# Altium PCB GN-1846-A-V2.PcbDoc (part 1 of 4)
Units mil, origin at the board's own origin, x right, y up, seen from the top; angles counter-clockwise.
Board outline 11624.17 x 2384.02 mil, 4 copper layers (Top, GND, VCC, Bottom), stack 40.7 mil thick; 450 components, 346 nets, 1652 pads, 832 vias.
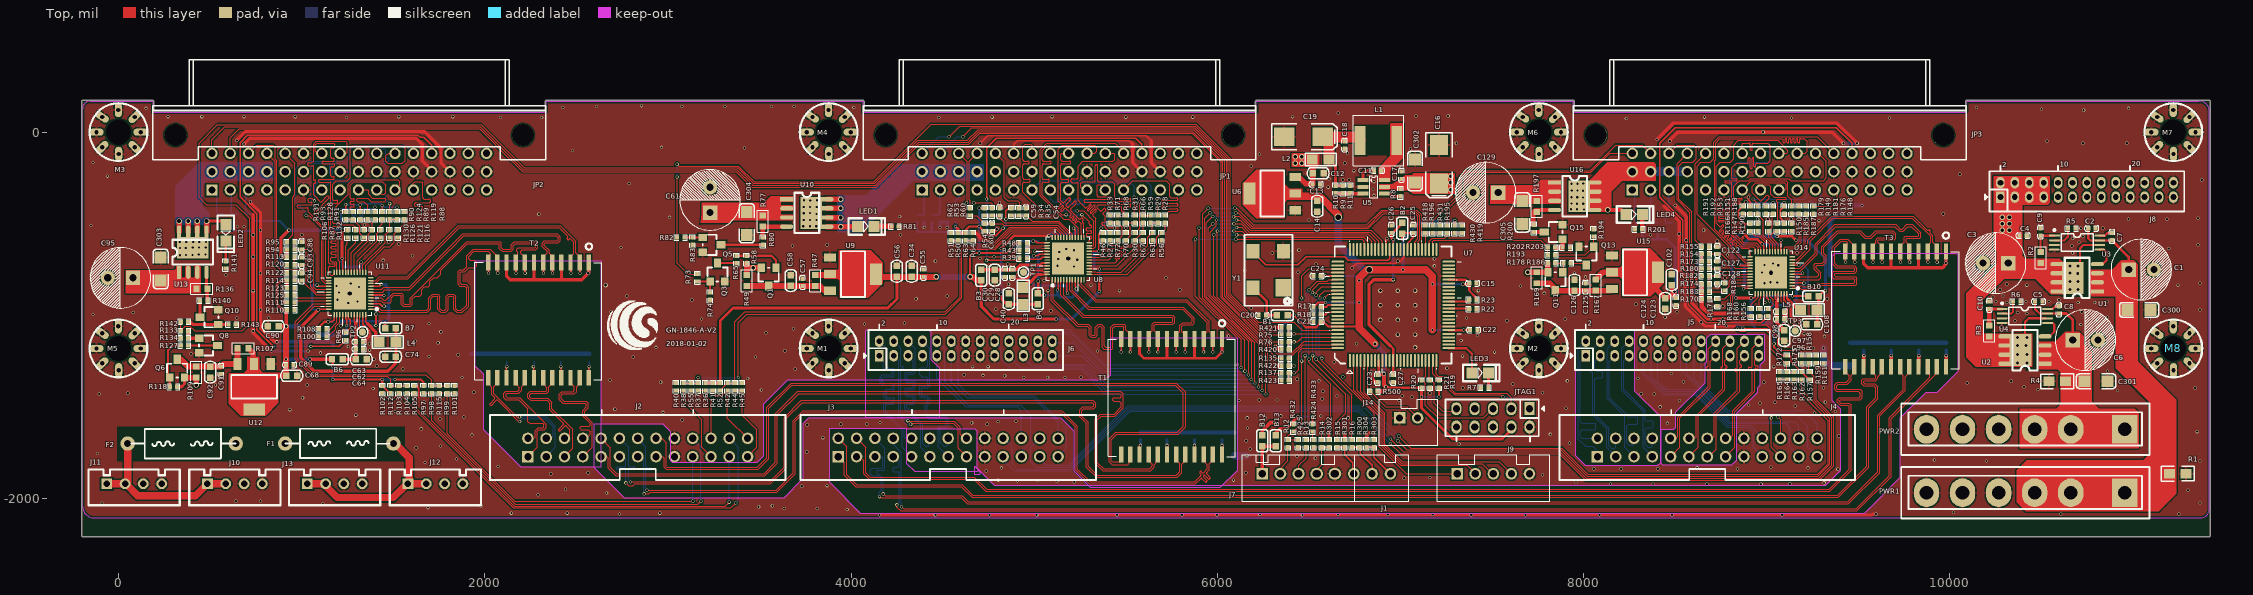
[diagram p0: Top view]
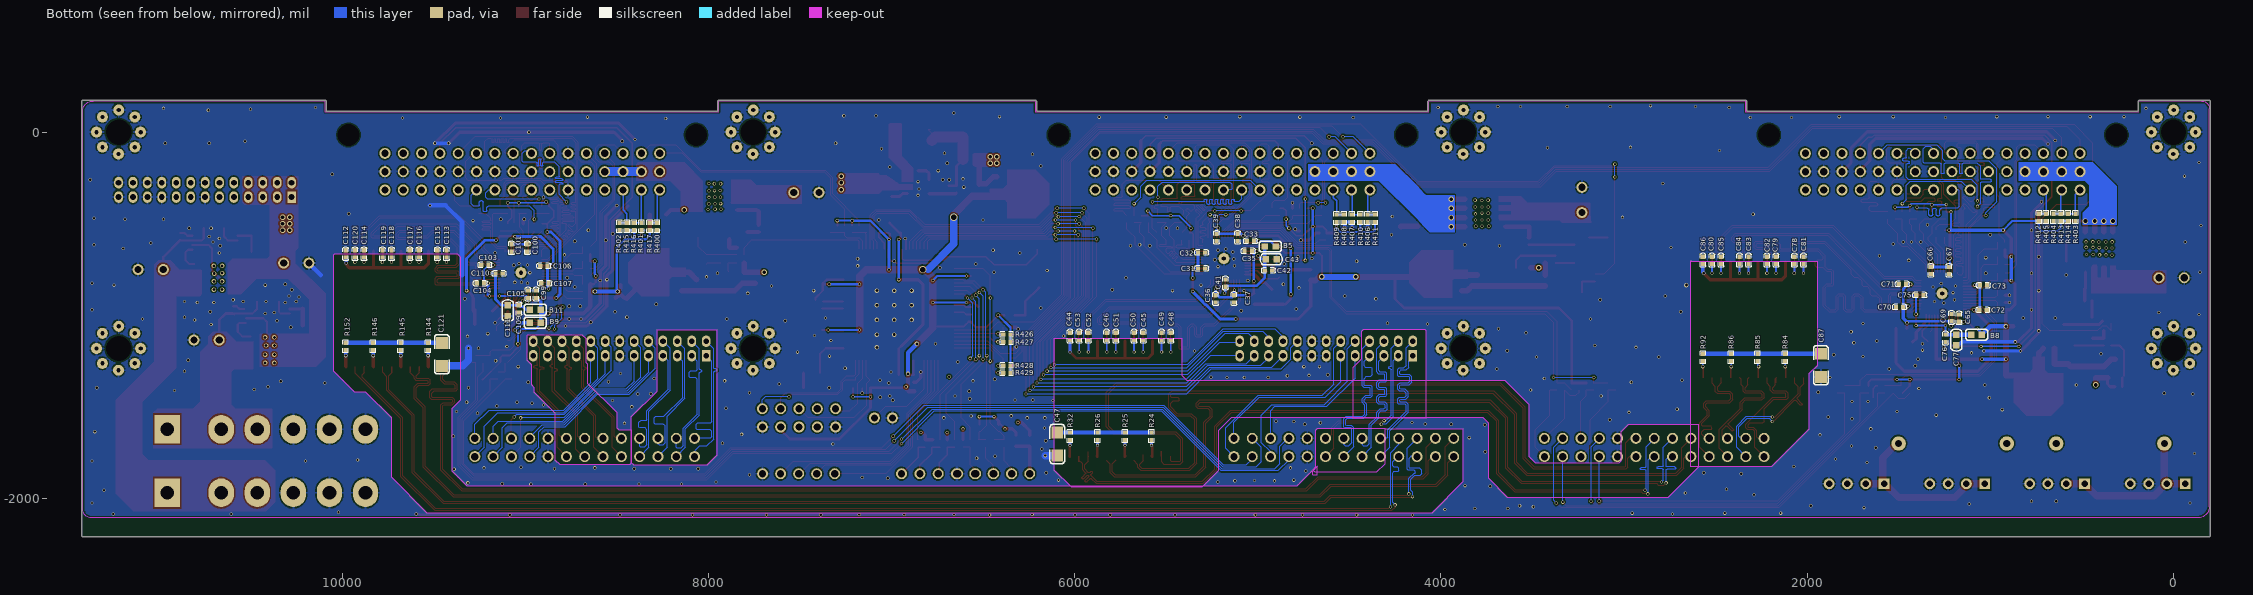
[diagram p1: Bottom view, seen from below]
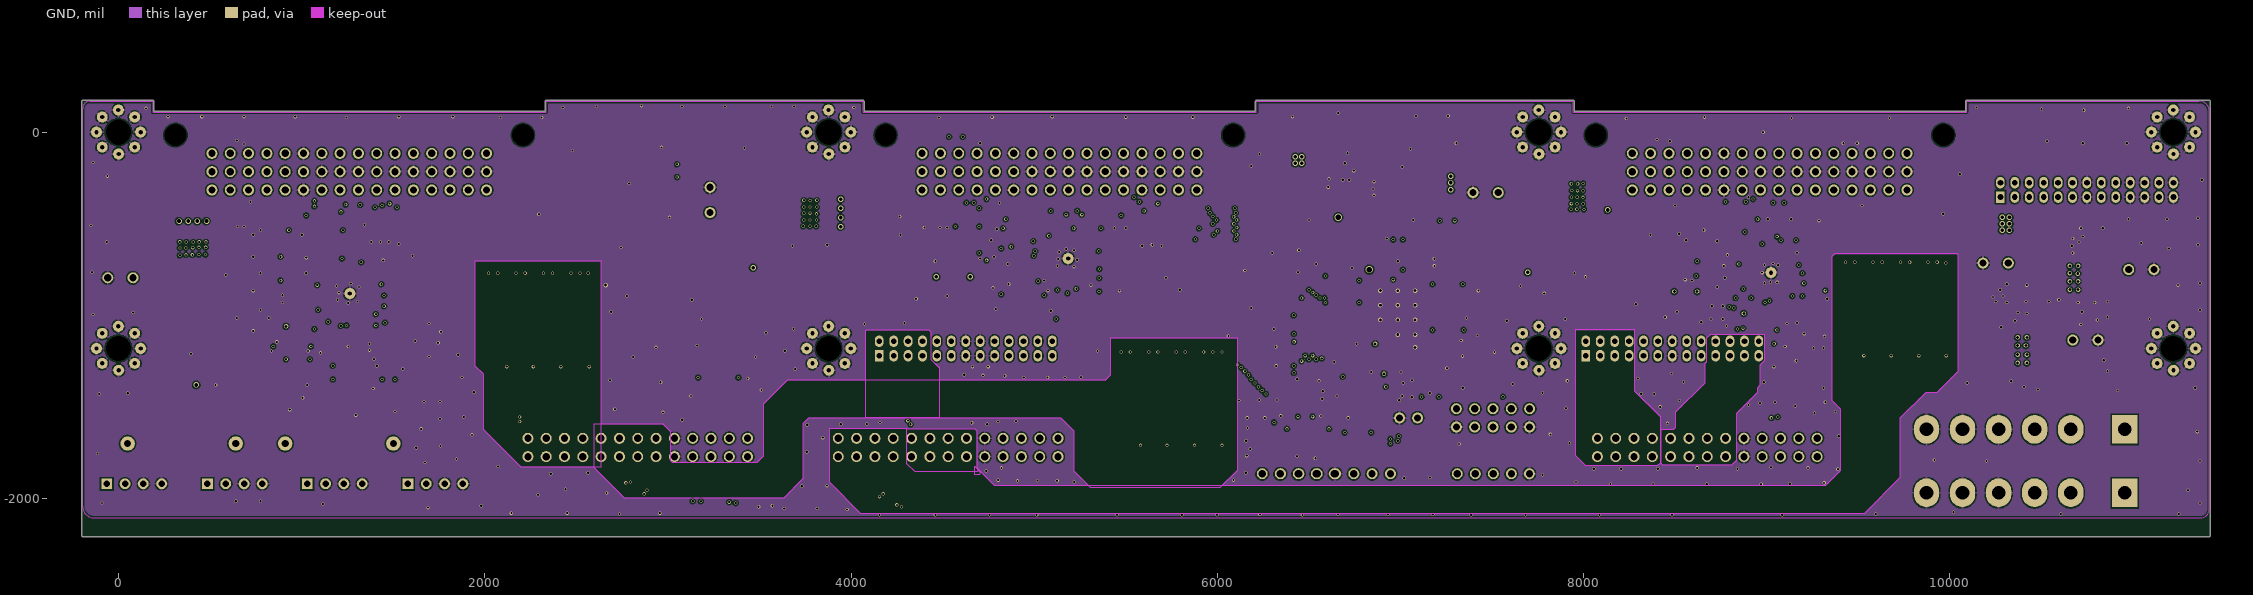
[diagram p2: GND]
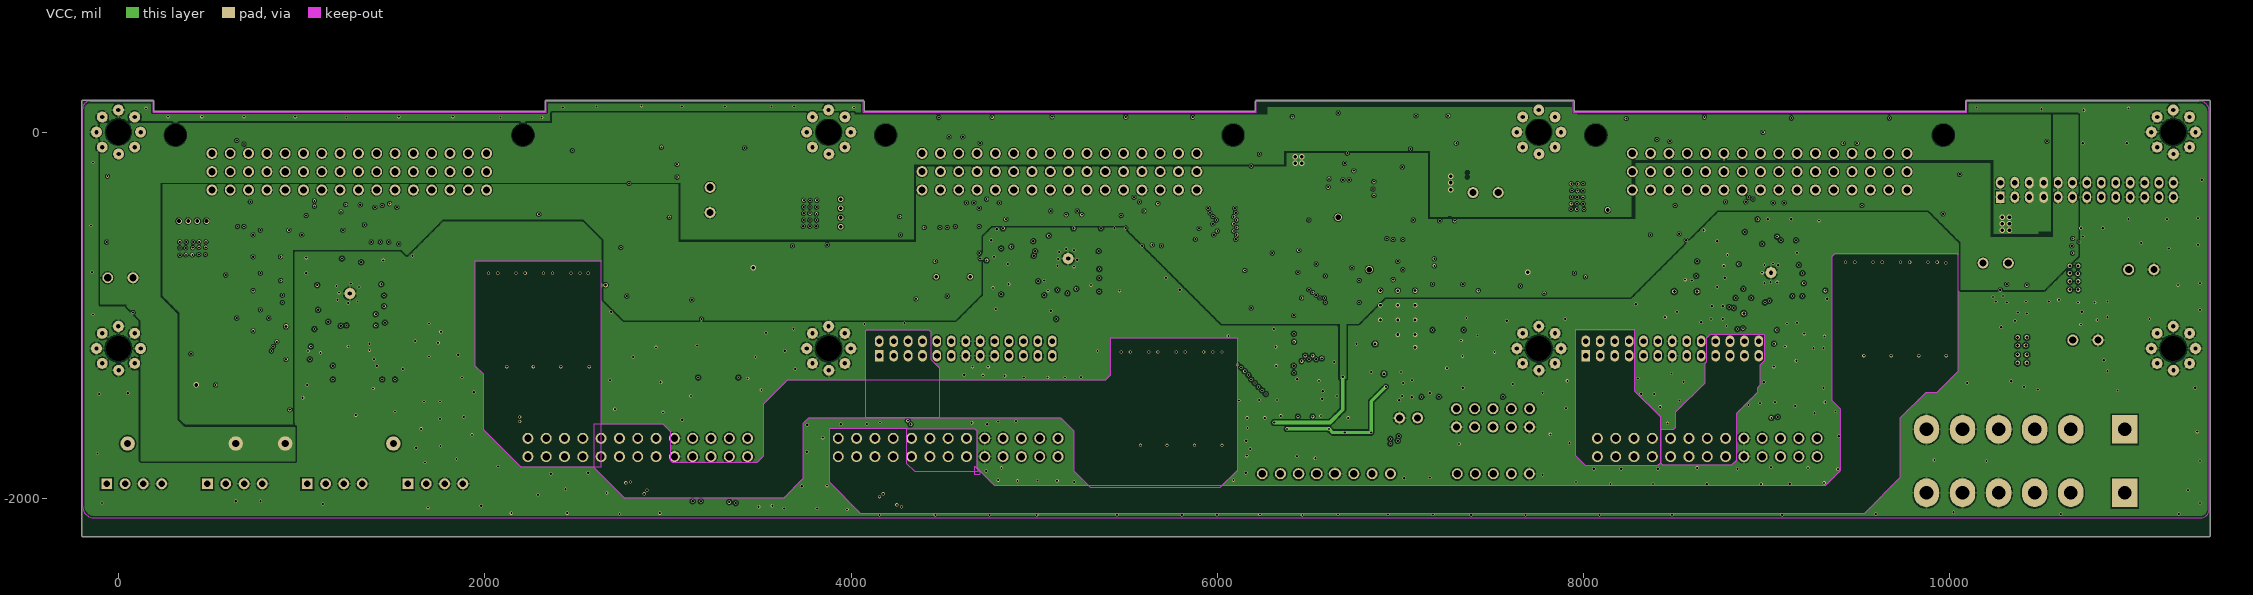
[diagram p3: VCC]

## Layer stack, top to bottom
Top: signal copper 1.35
Dielectric: core 10, FR-4, Dk 4.3
GND: signal copper 1.4
Dielectric: prepreg 12.6, FR-4, Dk 4.8
VCC: signal copper 1.4
Dielectric: core 12.6, FR-4, Dk 4.8
Bottom: signal copper 1.35

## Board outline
-201.85,-2204.72 -196.85,-2209.72 11417.32,-2209.72 11422.32,-2204.72 11422.32,169.29 11417.32,174.29 10090.55,174.29 10085.55,169.29 10085.55,115.24 7949.09,115.24 7949.09,169.29 7944.09,174.29 6212.6,174.29 6207.6,169.29 6207.6,115.24 4071.14,115.24 4071.14,169.29 4066.14,174.29 2334.25,174.29 2329.25,169.29 2329.25,115.24 193.19,115.24 193.19,169.29 188.19,174.29 -196.85,174.16 -201.85,169.16

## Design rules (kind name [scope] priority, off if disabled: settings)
Clearance "'Default' PADS rule_18" [All] p1: gap=5
ComponentClearance "'Default' PADS rule_12" [All] p1: gap=0 collisioncheckmode=3 verticalgap=0 showdistances=FALSE
FabricationTestPointUsage TestPointUsage [All] p1: valid=0 allowmultiple=FALSE
FabricationTestpoint Testpoint [All] p1: side=3 testpointundercomponent=TRUE minsize=40 maxsize=100 preferedsize=60 minholesize=0 maxholesize=40 preferedholesize=32 testpointgrid=1 allowsidetop=TRUE allowsidebottom=TRUE usegrid=TRUE gridtolerance=0.01
FlightTimeFalling "'Default' PADS rule_6" [All] p1: maximum=10.00
FlightTimeRising "'Default' PADS rule_5" [All] p1: maximum=10.00
Length "'Default' PADS rule" [All] p1: maxlimit=50000 minlimit=0
MaxMinImpedance "'Default' PADS rule_4" [All] p1: minimum=50.00 maximum=150.0
MinimumSolderMaskSliver [All] p1: minsoldermaskwidth=0
PlaneClearance "'Net' PADS rule_19" [InNet('GND')] p1: clearance=6
PlaneClearance "'Default' PADS rule_14" [All] p2: clearance=5
PlaneConnect "Power Plane Connect Style - pads with no thermal_20" [(Name='JTAG1-7') Or (Name='JTAG1-8') Or (Name='M1-1') Or (Name='M2-1') Or (Name='M3-1') Or (Name='M4-1') Or (Name='M5-1') Or (Name='M6-1') Or (Name='M7-1') Or (Name='M8-1')] p1: planeconnectstyle=Direct reliefexpansion=20 reliefentries=4 reliefconductorwidth=10 reliefairgap=10 // PAD - No Thermal Connect Rule
PlaneConnect "Power Plane Connect Style - pads with no thermal" [(Name='J7-5') Or (Name='JP1-A14') Or (Name='JP1-A15') Or (Name='JP1-A16') Or (Name='JP1-B5') Or (Name='JP1-B6') Or (Name='JP1-C1') Or (Name='JP1-C2') Or (Name='JP1-C3') Or (Name='JP1-C4') Or (Name='JP1-C5') Or (Name='JP1-C13') Or (Name='JP1-C14') Or (Name='JP1-C15') Or (Name='JP1-C16') Or (Name='JP1-0') Or (Name='JP1-0/2') Or (Name='JP2-A14') Or (Name='JP2-A15') Or (Name='JP2-A16') Or (Name='JP2-B5') Or (Name='JP2-B6') Or (Name='JP2-C1') Or (Name='JP2-C2') Or (Name='JP2-C3') Or (Name='JP2-C4') Or (Name='JP2-C5') Or (Name='JP2-C13') Or (Name='JP2-C14') Or (Name='JP2-C15') Or (Name='JP2-C16') Or (Name='JP2-0') Or (Name='JP2-0/2') Or (Name='JP3-A14') Or (Name='JP3-A15') Or (Name='JP3-A16') Or (Name='JP3-B5') Or (Name='JP3-B6') Or (Name='JP3-C1') Or (Name='JP3-C2') Or (Name='JP3-C3') Or (Name='JP3-C4') Or (Name='JP3-C5') Or (Name='JP3-C13') Or (Name='JP3-C14') Or (Name='JP3-C15') Or (Name='JP3-C16') Or (Name='JP3-0') Or (Name='JP3-0/2') Or (Name='JTAG1-6')] p2: planeconnectstyle=NoConnect reliefexpansion=20 reliefentries=4 reliefconductorwidth=10 reliefairgap=10 // PAD - No Thermal Connect Rule
PlaneConnect "Power Plane Connect Style - from global settings" [All] p3: planeconnectstyle=Direct reliefexpansion=20 reliefentries=4 reliefconductorwidth=15 reliefairgap=10
PolygonConnect PolygonConnect_1 [All vs isvia] p1: connectstyle=Direct reliefconductorwidth=10 reliefentries=4 polygonreliefangle="90 Angle"
PolygonConnect [All] p2: connectstyle=Relief reliefconductorwidth=10 reliefentries=4 polygonreliefangle="90 Angle"
RoomDefinition "P04 Power" [InComponentClass('P04 Power')] p1: confinementstyle=ConfineIn formatcopy=TRUE lockcomponents=FALSE outline -10196.85,-13767.85 -8196.85,-13767.85 -8196.85,-12767.85 -10196.85,-12767.85
RoomDefinition "P09 CONNECT & LED" [InComponentClass('P09 CONNECT & LED')] p2: confinementstyle=ConfineIn formatcopy=TRUE lockcomponents=FALSE outline -10196.85,-13767.85 -8196.85,-13767.85 -8196.85,-12767.85 -10196.85,-12767.85
RoomDefinition "P08 PHY 3" [InComponentClass('P08 PHY 3')] p3: confinementstyle=ConfineIn formatcopy=TRUE lockcomponents=FALSE outline -10196.85,-13767.85 -8196.85,-13767.85 -8196.85,-12767.85 -10196.85,-12767.85
RoomDefinition "P07 PHY 2" [InComponentClass('P07 PHY 2')] p4: confinementstyle=ConfineIn formatcopy=TRUE lockcomponents=FALSE outline -10196.85,-13767.85 -8196.85,-13767.85 -8196.85,-12767.85 -10196.85,-12767.85
RoomDefinition "P06 PHY 1" [InComponentClass('P06 PHY 1')] p5: confinementstyle=ConfineIn formatcopy=TRUE lockcomponents=FALSE outline -10196.85,-13767.85 -8196.85,-13767.85 -8196.85,-12767.85 -10196.85,-12767.85
RoutingLayers "'Default' PADS rule_10" [All] p1: top layer_v5=TRUE mid layer 1_v5=FALSE mid layer 2_v5=FALSE bottom layer_v5=TRUE
RoutingPriority "'Default' PADS rule_9" [All] p1: routingpriority=3
RoutingTopology "'Default' PADS rule_8" [All] p1: topology=Shortest
RoutingVias "'Default' PADS rule_11" [All] p1: holewidth=12 width=18 viastyle="Through Hole" minholewidth=12 minwidth=18 maxholewidth=12 maxwidth=18
SMDToCorner "'Default' PADS rule_16" [All] p1: distance=0
SMDToPlane "'Default' PADS rule_17" [All] p1: distance=50000
SilkToSilkClearance [All] p1: silktosilkclearance=0
SilkscreenOverComponentPads [All] p1: minsilkscreentomaskgap=0
SolderMaskExpansion [All] p1: expansion=4
Width "'Net' PADS rule" [InNet('GND')] p1: maxlimit=100 minlimit=5 preferedwidth=5
Width "'Default' PADS rule_13" [All] p2: maxlimit=100 minlimit=5 preferedwidth=5
17 further rules are at their usual default settings.

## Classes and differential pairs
component class "P09 CONNECT & LED": J2 J3 J4 J5 J6 J8 M1 M2 M3 M4 M5 M6 M7 M8
component class "P08 PHY 3": B9 B10 B11 C96 C97 C98 C99 C100 C101 C102 C103 C104 C105 C106 C107 C108 C109 C110 C111 C112 C113 C114 C115 C116 C117 C118 C119 C120 C121 C122 C123 C124 C125 C126 C127 C128 C129 C305 JP3 L5 LED4 Q11 Q13 Q15 R144 R145 R146 R147 R148 R149 R150 R151 R152 R153 R154 R155 R156 R157 R158 R159 R160 R161 R162 R163 R164 R165 R166 R167 R168 R169 R170 R171 R172 R173 R174 R175 R176 R178 R179 R180 R181 R182 R183 R184 R185 R186 R187 R188 R190 R191 R192 R193 R194 R195 R196 R197 R200 R201 R202 R203 R400 R401 R402 R415 R416 R417 R418 R419 R430 R431 T3 TP3 U14 U15 U16
component class "P07 PHY 2": B6 B7 B8 C62 C63 C64 C65 C66 C67 C68 C69 C70 C71 C72 C73 C74 C75 C76 C77 C78 C79 C80 C81 C82 C83 C84 C85 C86 C87 C88 C89 C90 C91 C92 C93 C94 C95 C303 JP2 L4 LED2 Q6 Q8 Q10 R84 R85 R86 R87 R88 R89 R90 R91 R92 R93 R94 R95 R96 R97 R98 R99 R100 R101 R102 R103 R104 R105 R106 R107 R108 R109 R110 R111 R112 R113 R114 R115 R116 R118 R119 R120 R121 R122 R123 R124 R125 R126 R127 R128 R130 R131 R132 R133 R134 R135 R136 R137 R140 R141 R142 R143 R403 R404 R405 R412 R413 R414 R422 R423 R428 R429 T2 TP2 U11 U12 U13
component class "P06 PHY 1": B3 B4 B5 C28 C29 C30 C31 C32 C33 C34 C35 C36 C37 C38 C39 C40 C41 C42 C43 C44 C45 C46 C47 C48 C49 C50 C51 C52 C53 C54 C55 C56 C57 C58 C59 C60 C61 C304 JP1 L3 LED1 Q1 Q3 Q5 R24 R25 R26 R27 R28 R29 R30 R31 R32 R33 R34 R35 R36 R37 R38 R39 R40 R41 R42 R43 R44 R45 R46 R47 R48 R49 R50 R51 R52 R53 R54 R55 R56 R58 R59 R60 R61 R62 R63 R64 R65 R66 R67 R68 R70 R71 R72 R73 R74 R75 R76 R77 R80 R81 R82 R83 R406 R407 R408 R409 R410 R411 R420 R421 R426 R427 T1 TP1 U8 U9 U10
component class "P05 CPLD": B1 B2 B12 B13 C20 C21 C22 C23 C24 C25 C26 C27 F1 F2 J1 J7 J9 J10 J11 J12 J13 J14 JTAG1 LED3 R7 R12 R13 R14 R15 R16 R17 R18 R19 R20 R21 R22 R23 R300 R301 R302 R303 R304 R424 R425 R432 R433 R500 U7 Y1
component class "P04 Power": C1 C2 C3 C4 C5 C6 C7 C8 C9 C10 C11 C12 C13 C14 C15 C16 C17 C18 C19 C300 C301 C302 L1 L2 PWR1 PWR2 R1 R2 R3 R4 R5 R6 R8 R9 R10 R11 U1 U2 U3 U4 U5 U6

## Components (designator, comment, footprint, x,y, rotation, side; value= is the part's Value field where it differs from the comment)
B1 "MGLB1608M600T3R0-LF" L0603 6355,-1000 r270 top
B2 "MGLB1608M600T3R0-LF" L0603 7010,-525 r180 top
B3 "MGLB1608M600T3R0-LF" L0603 4710,-780 r0 top
B4 "MGLB1608M600T3R0-LF" L0603 5020,-910 r0 top
B5 "MGLB1608M600T3R0-LF" L0603 4931.85,-624.16 r90 bottom
B6 "MGLB1608M600T3R0-LF" L0603 1195,-1240 r270 top
B7 "MGLB1608M600T3R0-LF" L0603 1485,-1070 r90 top
B8 "MGLB1608M600T3R0-LF" L0603 1075,-1105 r90 bottom
B9 "MGLB1608M600T3R0-LF" L0603 8945,-1040 r90 bottom
B10 "MGLB1608M600T3R0-LF" L0603 9255,-895 r90 top
B11 "MGLB1608M600T3R0-LF" L0603 8945,-970 r90 bottom
B12 "MGLB1608M600T3R0-LF" L0603 6245,-1685 r180 top
B13 "NC" L0603 6320,-1685 r180 top
C1 "220uF/25V/DIP" CE8X3.5 11045,-750 r0 top
C2 "0.1uF" 0402C 10755,-525 r0 top
C3 "220uF/25V/DIP" CE8X3.5 10250,-715 r180 top
C4 "0.1uF" 0402C 10380,-565 r0 top
C5 "0.1uF" 0402C 10465,-925 r0 top
C6 "220uF/25V/DIP" CE8X3.5 10740,-1135 r0 top
C7 "2200pF" 0402C 10885,-590 r90 top
C8 "2200pF" 0402C 10595,-990 r90 top
C9 "0.01uF" 0402C 10495,-565 r90 top
C10 "0.01uF" 0402C 10215,-965 r90 top
C11 "0.1uF/0603" 0402C 6855,-210 r0 top
C12 "10uF" C0603#1 6550,-225 r0 top
C13 "0.1uF" 0402C 6520,-285 r0 top
C14 "10uF" C0603#2 6545,-405 r270 top
C15 "0.1uF" 0402C 7375,-825 r0 top
C16 "22uF/25V/TD" C6032 7210,-280 r90 top
C17 "0.1uF" 0402C 7005,-255 r90 top
C18 "0.1uF" 0402C 6695,-50 r270 top
C19 "220uF/10V/TD" C6032 6575,-25 r180 top
C20 "0.1uF" 0402C 6225,-1000 r0 top
C21 "0.1uF" 0402C 6565,-1035 r180 top
C22 "0.1uF" 0402C 7380,-1080 r0 top
C23 "0.1uF" 0402C 6875,-1325 r270 top
C24 "0.1uF" 0402C 6565,-785 r180 top
C25 "0.1uF" 0402C 7070,-550 r90 top
C26 "0.1uF" 0402C 6950,-550 r90 top
C27 "0.1uF" 0402C 6960,-1325 r270 top
C28 "0.1uF" 0402C 4880,-750 r270 top
C29 "0.1uF" 0402C 4840,-750 r270 top
C30 "10uF" C0603#2 4785,-780 r270 top
C31 "0.1uF" 0402C 5326.38,-744.16 r180 bottom
C32 "0.1uF" 0402C 5326.38,-657.16 r180 bottom
C33 "0.1uF" 0402C 5020,-595 r0 bottom
C34 "10uF" C0603#2 4330,-760 r90 top
C35 "0.1uF" 0402C 5031.85,-649.16 r0 bottom
C36 "0.1uF" 0402C 5230,-890 r270 bottom
C37 "0.1uF" 0402C 5130,-890 r270 bottom
C38 "0.1uF" 0402C 5110,-555 r270 bottom
C39 "0.1uF" 0402C 5225,-555 r270 bottom
C40 "10uF" C0603#2 4860,-910 r90 top
C41 "0.1uF" 0402C 5176.85,-844.16 r90 bottom
C42 "0.1uF" 0402C 4961.38,-755 r180 bottom
C43 "10uF" C0603#2 4926.85,-694.16 r180 bottom
C44 "0.1uF" 0402C 6025,-1135 r90 bottom
C45 "nc" 0402C 5625,-1095 r270 bottom
C46 "nc" 0402C 5825,-1095 r270 bottom
C47 "1000pF/1KV" C1206 6095,-1640 r270 bottom
C48 "nc" 0402C 5475,-1095 r270 bottom
C49 "nc" 0402C 5525,-1095 r270 bottom
C50 "nc" 0402C 5675,-1095 r270 bottom
C51 "nc" 0402C 5775,-1095 r270 bottom
C52 "nc" 0402C 5925,-1095 r270 bottom
C53 "nc" 0402C 5975,-1095 r270 bottom
C54 "0.1uF" 0402C 4955,-415 r270 top
C55 "0.1uF" 0402C 4395,-790 r90 top
C56 "10uF" C0603#2 4250,-760 r90 top
C57 "0.1uF" 0402C 3735,-840 r90 top
C58 "10uF" C0603#2 3670,-810 r90 top
C59 "nc" 0402C 4810,-415 r270 top
C60 "nc" 0402C 4770,-540 r90 top
C61 "220uF/25V/DIP" CE8X3.5 3230,-370 r90 top
C62 "0.1uF" 0402C 1295,-1185 r0 top
C63 "0.1uF" 0402C 1295,-1145 r0 top
C64 "10uF" C0603#2 1325,-1240 r0 top
C65 "0.1uF" 0402C 1170,-1035 r90 bottom
C66 "0.1uF" 0402C 1325,-735 r270 bottom
C67 "0.1uF" 0402C 1225,-735.47 r270 bottom
C68 "10uF" C0603#2 945,-1330 r0 top
C69 "0.1uF" 0402C 1212.56,-1032.91 r90 bottom
C70 "0.1uF" 0402C 1475,-955 r0 bottom
C71 "0.1uF" 0402C 1460,-830 r0 bottom
C72 "0.1uF" 0402C 1059.83,-970.17 r180 bottom
C73 "0.1uF" 0402C 1057.68,-835.84 r180 bottom
C74 "10uF" C0603#2 1485,-1225 r180 top
C75 "0.1uF" 0402C 1404.53,-890 r180 bottom
C76 "0.1uF" 0402C 1245,-1105.47 r270 bottom
C77 "10uF" C0603#2 1185,-1135 r270 bottom
C78 "nc" 0402C 2070,-680 r270 bottom
C79 "nc" 0402C 2170,-680 r270 bottom
C80 "nc" 0402C 2520,-680 r270 bottom
C81 "nc" 0402C 2020,-680 r270 bottom
C82 "nc" 0402C 2220,-680 r270 bottom
C83 "nc" 0402C 2320,-680 r270 bottom
C84 "nc" 0402C 2370,-680 r270 bottom
C85 "nc" 0402C 2470,-680 r270 bottom
C86 "0.1uF" 0402C 2570,-720 r90 bottom
C87 "1000pF/1KV" C1206 1925,-1210 r270 bottom
C88 "0.1uF" 0402C 1000,-600 r270 top
C89 "0.1uF" 0402C 915,-1270 r0 top
C90 "10uF" C0603#2 845,-1060 r180 top
C91 "0.1uF" 0402C 560,-1280 r270 top
C92 "10uF" C0603#2 500,-1310 r270 top
C93 "nc" 0402C 1000,-685 r270 top
C94 "nc" 0402C 1000,-770 r270 top
C95 "220uF/25V/DIP" CE8X3.5 10,-795 r180 top
C96 "0.1uF" 0402C 9055,-1020 r0 top
C97 "0.1uF" 0402C 9055,-980 r0 top
C98 "10uF" C0603#2 9095,-1110 r270 top
C99 "0.1uF" 0402C 8940,-905 r90 bottom
C100 "0.1uF" 0402C 8988.39,-612.32 r270 bottom
C101 "0.1uF" 0402C 9075,-612.32 r270 bottom
C102 "10uF" C0603#2 8480,-805 r90 top
C103 "0.1uF" 0402C 9200,-725 r0 bottom
C104 "0.1uF" 0402C 9225,-825 r0 bottom
C105 "0.1uF" 0402C 8985,-905 r90 bottom
C106 "0.1uF" 0402C 8878.02,-730 r0 bottom
C107 "0.1uF" 0402C 8872.55,-825 r0 bottom
C108 "10uF" C0603#2 9245,-1050 r180 top
C109 "0.1uF" 0402C 9035,-945 r270 bottom
C110 "0.1uF" 0402C 9162.55,-772.22 r180 bottom
C111 "10uF" C0603#2 9095,-975 r270 bottom
C112 "0.1uF" 0402C 9980,-685 r90 bottom
C113 "nc" 0402C 9430,-645 r270 bottom
C114 "nc" 0402C 9880,-645 r270 bottom
C115 "nc" 0402C 9480,-645 r270 bottom
C116 "nc" 0402C 9580,-645 r270 bottom
C117 "nc" 0402C 9630,-645 r270 bottom
C118 "nc" 0402C 9730,-645 r270 bottom
C119 "nc" 0402C 9780,-645 r270 bottom
C120 "nc" 0402C 9930,-645 r270 bottom
C121 "1000pF/1KV" C1206 9455,-1150 r270 bottom
C122 "0.1uF" 0402C 8730,-625 r270 top
C123 "0.1uF" 0402C 8505,-905 r270 top
C124 "10uF" C0603#2 8445,-935 r270 top
C125 "0.1uF" 0402C 8010,-865 r90 top
C126 "10uF" C0603#2 7950,-835 r90 top
C127 "nc" 0402C 8730,-705 r270 top
C128 "nc" 0402C 8730,-825 r90 top
C129 "220uF/25V/DIP" CE8X3.5 7465,-330 r180 top
C300 "0.1uF" C1206 10970,-970 r0 top
C301 "0.1uF" C1206 10735,-1360 r0 top
C302 "nc" C1206 7080,-275 r90 top
C303 "10UF" C1206 230,-810 r90 top
C304 "10UF" C1206 3430,-435 r270 top
C305 "10UF" C1206 7665,-375 r270 top
F1 "Fuse 1" F15 910,-1700 r0 top
F2 "Fuse 1" F15 640,-1700 r180 top
J1 "8PIN_2.54MM" CON8_2D54MM_G 6245,-1865 r0 top
J2 "CON26A" HERDER2X13 2235,-1771.65 r0 top locked
J3 "CON26A" HERDER2X13 3930,-1771.65 r0 top locked
J4 "CON26A" HERDER2X13 8075,-1771.65 r0 top locked
J5 "CON14" HERDER13X2-2.0 8011.81,-1220.47 r0 top locked
J6 "CON14" HERDER13X2-2.0 4153.54,-1220.47 r0 top
J7 "5PIN_2.54MM" CON5_2D54MM_G 6245,-1865 r0 top
J8 "CON14" HERDER13X2-2.0 10275.59,-354.33 r0 top locked
J9 "5PIN_2.54MM" CON5_2D54MM_G 7310,-1865 r0 top
J10 "4PIN_2.54MM" SIP4 485,-1920 r0 top
J11 "4PIN_2.54MM" SIP4 -65,-1920 r0 top
J12 "4PIN_2.54MM" SIP4 1580,-1920 r0 top
J13 "4PIN_2.54MM" SIP4 1030,-1920 r0 top
J14 "2PIN_2.54MM" CN2 6995,-1560 r0 top
JP1 "3348RFRS-029" 3348RFRS-029 5137.8,-215.41 r180 top locked
JP2 "3348RFRS-029" 3348RFRS-029 1259.84,-215.52 r180 top locked
JP3 "3348RFRS-029" 3348RFRS-029 9015.75,-215.52 r180 top locked
JTAG1 "2x5_2.54MM" HERDER5X2 7705,-1510 r180 top
L1 "MPIT6045-100M-LF" MPI6045 6880,-45 r180 top
L2 "MPIT5040-3R3N-LF" FB0805 6610,-150 r180 top
L3 "CBC3225T4R7MR" FB0805 4940,-940 r90 top
L4 "CBC3225T4R7MR" FB0805 1515,-1145 r180 top
L5 "CBC3225T4R7MR" FB0805 9275,-970 r180 top
LED1 "GRE/0805" LED0805 4125,-515 r180 top
LED2 "GRE/0805" LED0805 585,-595 r90 top
LED3 "GRE/0805" LED0805 7480,-1315 r180 top
LED4 "GRE/0805" LED0805 8320,-450 r180 top
M1 "HOLE-8STARS" HK 3877.95,-1181.1 r0 top locked
M2 "HOLE-8STARS" HK 7755.91,-1181.1 r0 top locked
M3 "HOLE-8STARS" HK 0,0 r0 top locked
M4 "HOLE-8STARS" HK 3877.95,0 r0 top locked
M5 "HOLE-8STARS" HK 0,-1181.1 r0 top locked
M6 "HOLE-8STARS" HK 7755.91,0 r0 top locked
M7 "HOLE-8STARS" HK 11220.47,0 r0 top locked
M8 "HOLE-8STARS" HK 11220.47,-1181.1 r0 top locked
PWR1 "POWER_6P" TJC2-6 10955,-1968.5 r180 top
PWR2 "POWER_6P" TJC2-6 10955,-1622.05 r180 top
Q1 "P6403FMG" SOT23 3550,-790 r180 top
Q3 "MMBT3904" SOT23 3270,-765 r0 top
Q5 "MMBT3904" SOT23 3240,-615 r270 top
Q6 "P6403FMG" SOT23 320,-1290 r0 top
Q8 "MMBT3904" SOT23 490,-1165 r270 top
Q10 "MMBT3904" SOT23 495,-1010 r90 top
Q11 "P6403FMG" SOT23 7845,-815 r180 top
Q13 "MMBT3904" SOT23 8015,-675 r180 top
Q15 "MMBT3904" SOT23 7835,-545 r90 top
R1 "nc" 0805 11200,-1865 r270 top
R2 "10" R0603 10495,-685 r90 top
R3 "10" R0603 10215,-1085 r90 top
R4 "nc" 0805 10630,-1360 r90 top
R5 "40.2K/1%" 0402R 10645,-525 r0 top
R6 "40.2K/1%" 0402R 10345,-925 r0 top
R7 "5.1K" 0402R 7440,-1395 r0 top
R8 "100K" 0402R 7000,-310 r270 top
R9 "62K/1%" 0402R 6685.51,-292.35 r270 top
R10 "nc" 0402R 6645.51,-292.35 r270 top
R11 "7.5K/1%" 0402R 6725.51,-332.35 r90 top
R12 "100" 0402R 6385,-1680 r270 top
R13 "100" 0402R 6485,-1680 r270 top
R14 "100" 0402R 6570,-1680 r270 top
R15 "100" 0402R 6655,-1680 r270 top
R16 "100" 0402R 6735,-1680 r270 top
R17 "nc" 0402R 6525,-955 r0 top
R18 "nc" 0402R 6525,-995 r0 top
R19 "4.7K" 0402R 7210,-1395 r90 top
R20 "4.7K" 0402R 7115,-1395 r90 top
R21 "4.7K" 0402R 7160,-1355 r270 top
R22 "nc" 0402R 7375,-965 r0 top
R23 "nc" 0402R 7375,-915 r0 top
R24 "75" 0402R 5580,-1680 r90 bottom
R25 "75" 0402R 5725,-1680 r90 bottom
R26 "75" 0402R 5875,-1680 r90 bottom
R27 "33" 0402R 5415,-550 r270 top
R28 "33" 0402R 5715,-455 r270 top
R29 "33" 0402R 5675,-455 r270 top
R30 "33" 0402R 5550,-550 r270 top
R31 "33" 0402R 5550,-455 r270 top
R32 "75" 0402R 6025,-1680 r90 bottom
R33 "33" 0402R 5415,-455 r270 top
R34 "nc" 0402R 4875,-415 r270 top
R35 "33" 0402R 4915,-415 r270 top
R36 "nc" 0402R 3205,-1370 r270 top
R37 "0" 0402R 3165,-1370 r270 top
R38 "nc" 0402R 3085,-1370 r270 top
R39 "33" 0402R 4920,-690 r0 top
R40 "4.7K" 0402R 3045,-1370 r270 top
R41 "4.7K" 0402R 3245,-1370 r270 top
R42 "nc" 0402R 3325,-1370 r270 top
R43 "2.49K/1%" 0402R 4920,-645 r0 top
R44 "0" 0402R 3365,-1370 r270 top
R45 "nc" 0402R 3405,-1370 r270 top
R46 "4.7K" 0402R 5375,-590 r90 top
R47 "nc" R0603 3805,-810 r270 top
R48 "4.7K" 0402R 4960,-605 r180 top
R49 "nc" R0603 3430,-810 r90 top
R50 "4.7K" 0402R 4585,-590 r90 top
R51 "nc" 0402R 4545,-590 r90 top
R52 "4.7K" 0402R 3285,-1410 r90 top
R53 "1.5K" 0402R 4730,-455 r90 top
R54 "1.5K" 0402R 4730,-500 r270 top
R55 "4.7K" 0402R 3125,-1370 r270 top
R56 "4.7K" 0402R 5695,-550 r270 top
R58 "100K" 0402R 3430,-715 r90 top
R59 "4.7K" 0402R 5635,-495 r90 top
R60 "33" 0402R 4770,-415 r270 top
R61 "nc" 0402R 5645,-550 r270 top
R62 "33" 0402R 4650,-415 r270 top
R63 "4.7K" 0402R 4625,-590 r90 top
R64 "nc" 0402R 4665,-590 r90 top
R65 "10K" 0402R 3375,-675 r270 top
R66 "4.7K" 0402R 5595,-495 r90 top
R67 "nc" 0402R 5595,-550 r270 top
R68 "4.7K" 0402R 5500,-495 r90 top
R70 "nc" 0402R 5500,-590 r90 top
R71 "4.7K" 0402R 5455,-495 r90 top
R72 "nc" 0402R 5455,-590 r90 top
R73 "2K" 0402R 3160,-815 r90 top
R74 "1K" 0402R 3230,-915 r90 top
R75 "100" 0402R 6350,-1105 r0 top
R76 "100" 0402R 6350,-1145 r0 top
R77 "100K" R0603 3518.15,-485.84 r90 top
R80 "0" 0402R 3520,-615 r90 top
R81 "10K" 0402R 4260,-515 r180 top
R82 "2K" 0402R 3090,-575 r180 top
R83 "1K" 0402R 3135,-615 r90 top
R84 "75" 0402R 2120,-1250 r90 bottom
R85 "75" 0402R 2270,-1250 r90 bottom
R86 "75" 0402R 2415,-1250 r90 bottom
R87 "33" 0402R 1295,-535 r270 top
R88 "33" 0402R 1560,-435 r270 top
R89 "33" 0402R 1480,-435 r270 top
R90 "33" 0402R 1400,-435 r270 top
R91 "33" 0402R 1360,-435 r270 top
R92 "75" 0402R 2570,-1250 r90 bottom
R93 "33" 0402R 1280,-435 r270 top
R94 "nc" 0402R 920,-640 r0 top
R95 "33" 0402R 920,-600 r0 top
R96 "33" 0402R 1240,-1135 r90 top
R97 "nc" 0402R 1665,-1385 r270 top
R98 "0" 0402R 1710,-1385 r270 top
R99 "nc" 0402R 1795,-1385 r270 top
R100 "2.49K/1%" 0402R 1095,-1115 r0 top
R101 "4.7K" 0402R 1835,-1385 r270 top
R102 "4.7K" 0402R 1440,-1385 r270 top
R103 "nc" 0402R 1530,-1385 r270 top
R104 "0" 0402R 1575,-1385 r270 top
R105 "nc" 0402R 1615,-1385 r270 top
R106 "4.7K" 0402R 1250,-575 r90 top
R107 "nc" R0603 680,-1180 r180 top
R108 "4.7K" 0402R 1135,-1075 r180 top
R109 "nc" R0603 425,-1310 r270 top
R110 "4.7K" 0402R 960,-970 r180 top
R111 "nc" 0402R 960,-930 r180 top
R112 "4.7K" 0402R 1485,-1385 r270 top
R113 "1.5K" 0402R 960,-680 r180 top
R114 "1.5K" 0402R 960,-810 r180 top
R115 "4.7K" 0402R 1750,-1385 r270 top
R116 "4.7K" 0402R 1525,-535 r270 top
R118 "100K" 0402R 320,-1390 r180 top
R119 "4.7K" 0402R 1520,-475 r90 top
R120 "33" 0402R 920,-725 r0 top
R121 "nc" 0402R 1480,-535 r270 top
R122 "33" 0402R 920,-770 r0 top
R123 "4.7K" 0402R 960,-850 r180 top
R124 "4.7K" 0402R 1440,-475 r90 top
R125 "nc" 0402R 960,-890 r180 top
R126 "nc" 0402R 1430,-535 r270 top
R127 "10K" 0402R 340,-1165 r0 top
R128 "4.7K" 0402R 1320,-475 r90 top
R130 "nc" 0402R 1385,-535 r270 top
R131 "4.7K" 0402R 1240,-475 r90 top
R132 "nc" 0402R 1340,-575 r90 top
R133 "2K" 0402R 380,-1085 r180 top
R134 "1K" 0402R 340,-1125 r0 top
R135 "100" 0402R 6350,-1235 r0 top
R136 "100K" R0603 455,-855 r180 top
R137 "100" 0402R 6350,-1315 r0 top
R140 "0" 0402R 445,-920 r0 top
R141 "10K" 0402R 585,-745 r90 top
R142 "2K" 0402R 380,-1035 r180 top
R143 "1K" 0402R 640,-1050 r180 top
R144 "75" 0402R 9530,-1190 r90 bottom
R145 "75" 0402R 9680,-1190 r90 bottom
R146 "75" 0402R 9830,-1190 r90 bottom
R147 "33" 0402R 8950,-500 r270 top
R148 "33" 0402R 9255,-405 r270 top
R149 "33" 0402R 9135,-405 r270 top
R150 "33" 0402R 9055,-500 r270 top
R151 "33" 0402R 8995,-405 r270 top
R152 "75" 0402R 9980,-1190 r90 bottom
R153 "33" 0402R 8950,-405 r270 top
R154 "nc" 0402R 8645,-665 r0 top
R155 "33" 0402R 8645,-625 r0 top
R156 "33" 0402R 9005,-1005 r90 top
R157 "nc" 0402R 9235,-1350 r90 top
R158 "0" 0402R 9230,-1220 r270 top
R159 "nc" 0402R 9270,-1220 r270 top
R160 "2.49K/1%" 0402R 8960,-1005 r90 top
R161 "4.7K" 0402R 9310,-1220 r270 top
R162 "4.7K" 0402R 9190,-1310 r270 top
R163 "nc" 0402R 9150,-1310 r270 top
R164 "0" 0402R 9110,-1310 r270 top
R165 "nc" 0402R 9070,-1310 r270 top
R166 "4.7K" 0402R 8910,-540 r90 top
R167 "nc" R0603 8065,-835 r270 top
R168 "4.7K" 0402R 8915,-965 r270 top
R169 "nc" R0603 7745,-795 r90 top
R170 "4.7K" 0402R 8685,-910 r180 top
R171 "nc" 0402R 8730,-910 r270 top
R172 "4.7K" 0402R 9110,-1260 r90 top
R173 "1.5K" 0402R 8685,-705 r180 top
R174 "1.5K" 0402R 8685,-830 r180 top
R175 "4.7K" 0402R 9190,-1220 r270 top
R176 "4.7K" 0402R 9215,-445 r90 top
R178 "100K" 0402R 7805,-715 r0 top
R179 "4.7K" 0402R 9095,-445 r90 top
R180 "33" 0402R 8645,-745 r0 top
R181 "nc" 0402R 9175,-445 r90 top
R182 "33" 0402R 8645,-785 r0 top
R183 "4.7K" 0402R 8685,-870 r180 top
R184 "nc" 0402R 8770,-865 r90 top
R185 "4.7K" 0402R 9095,-540 r90 top
R186 "10K" 0402R 7890,-715 r0 top
R187 "nc" 0402R 9135,-540 r90 top
R188 "4.7K" 0402R 9035,-445 r90 top
R190 "nc" 0402R 9010,-540 r90 top
R191 "4.7K" 0402R 8870,-445 r90 top
R192 "nc" 0402R 8910,-445 r90 top
R193 "2K" 0402R 7845,-670 r180 top
R194 "1K" 0402R 8055,-530 r270 top
R195 "100" 0402R 7255,-510 r270 top
R196 "100" 0402R 7175,-510 r270 top
R197 "100K" R0603 7745,-405 r90 top
R200 "0" 0402R 7730,-545 r90 top
R201 "10K" 0402R 8280,-530 r0 top
R202 "2K" 0402R 7845,-630 r180 top
R203 "1K" 0402R 7925,-630 r180 top
R300 "5K1" 0402R 6775,-1680 r270 top
R301 "5K1" 0402R 6695,-1680 r270 top
R302 "5K1" 0402R 6610,-1680 r270 top
R303 "100" 0402R 6855,-1680 r270 top
R304 "5K1" 0402R 6815,-1680 r270 top
R400 "nc" 0402R 8280,-495 r270 bottom
R401 "nc" 0402R 8365,-495 r270 bottom
R402 "nc" 0402R 8485,-495 r270 bottom
R403 "nc" 0402R 535,-445 r270 bottom
R404 "nc" 0402R 655,-445 r270 bottom
R405 "nc" 0402R 695,-445 r270 bottom
R406 "nc" 0402R 4400,-450 r270 bottom
R407 "nc" 0402R 4485,-450 r270 bottom
R408 "nc" 0402R 4530,-450 r270 bottom
R409 "10K/NC" 0402R 4570,-450 r270 bottom
R410 "10K/NC" 0402R 4440,-450 r270 bottom
R411 "10K/NC" 0402R 4360,-450 r270 bottom
R412 "10K/NC" 0402R 735,-445 r270 bottom
R413 "10K/NC" 0402R 615,-445 r270 bottom
R414 "10K/NC" 0402R 575,-445 r270 bottom
R415 "10K/NC" 0402R 8445,-495 r270 bottom
R416 "10K/NC" 0402R 8405,-495 r270 bottom
R417 "10K/NC" 0402R 8320,-495 r270 bottom
R418 "5K1" 0402R 7135,-550 r90 top
R419 "5K1" 0402R 7335,-550 r90 top
R420 "5K1" 0402R 6390,-1185 r180 top
R421 "5K1" 0402R 6390,-1065 r180 top
R422 "5K1" 0402R 6390,-1275 r180 top
R423 "5K1" 0402R 6390,-1355 r180 top
R424 "5K1" 0402R 6525,-1720 r90 top
R425 "5K1" 0402R 6440,-1720 r90 top
R426 "5K1(NC)" 0402R 6390,-1105 r180 bottom
R427 "5K1(NC)" 0402R 6390,-1145 r180 bottom
R428 "5K1(NC)" 0402R 6390,-1275 r180 bottom
R429 "5K1(NC)" 0402R 6390,-1315 r180 bottom
R430 "5K1(NC)" 0402R 7295,-550 r90 top
R431 "5K1(NC)" 0402R 7215,-550 r90 top
R432 "5K1(NC)" 0402R 6415,-1595 r270 top
R433 "5K1(NC)" 0402R 6520,-1595 r270 top
R500 "4.7K" 0402R 6835,-1415 r0 top
T1 "PULSE H5007" H5007-H 5750,-1445 r180 top locked
T2 "PULSE H5007" H5007-H 2293.15,-1025.84 r180 top
T3 "PULSE H5007" H5007-H 9703.15,-965.84 r180 top
TP1 "T POINT A" TP_G 4941.59,-764.87 r180 top
TP2 "T POINT A" TP_G 1331.95,-1091.57 r270 top
TP3 "T POINT A" TP_G 9155,-1085 r270 top
U1 "SI7139" POWERPAKSO8 10805,-870 r180 top
U2 "SI7139" POWERPAKSO8 10520,-1265 r180 top
U3 "TPS2142PW" TSSOP-8 10570,-565 r0 top
U4 "TPS2142PW" TSSOP-8 10285,-965 r0 top
U5 "SY8113B" SOT23_6_G 6853.66,-298.18 r0 top
U6 "AS1117-3.3" SOT223 6300,-335 r90 top
U7 "EPM240T100C5" TQFP-100P 6723.15,-1245.84 r90 top
U8 "RTL8211D" QFN-48P-RTL8211 5185,-690 r0 top
U9 "AS1117-3.3" SOT223 4010,-775 r270 top
U10 "SI7139" POWERPAKSO8 3648.15,-365.84 r0 top
U11 "RTL8211D" QFN-48P-RTL8211 1263.15,-880.84 r90 top
U12 "AS1117-3.3" SOT223 740,-1390 r180 top
U13 "SI7139" POWERPAKSO8 330.24,-765.21 r90 top
U14 "RTL8211D" QFN-48P-RTL8211 9023.39,-766.85 r90 top
U15 "AS1117-3.3" SOT223 8280,-765 r270 top
U16 "SI7139" POWERPAKSO8 7841.15,-274.84 r0 top
Y1 "NC/25MHZ/20PPM" SCXO_7.0X5.0 6360,-850 r90 top

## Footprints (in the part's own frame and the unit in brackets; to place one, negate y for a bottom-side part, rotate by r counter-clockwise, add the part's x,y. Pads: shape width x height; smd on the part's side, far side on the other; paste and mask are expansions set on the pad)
0402C [mil]
  rect 23x23 smd: 1(0,0) 2(40,0)
  silkscreen extent -18,-15 58,15
0402R [mil]
  rect 23x23 smd: 1(0,0) 2(40,0)
  silkscreen extent -15,-15 55,15
0805 [mil]
  rect 50x60 smd: 1(0,-0.31) 2(0,89.69)
  silkscreen extent -40,-45 40,135
3348RFRS-029 [mil]
  round 118.11 / inner round 60 / far side round 60 hole 118.11: 0(948.82,-200) 0/2(-948.82,-200)
  round 62 / inner round 60 / far side round 60 hole 39.37: A1(750,-100) A2(650,-100) A3(550,-100) A4(450,-100) A5(350,-100) A6(250,-100) A7(150,-100) A8(50,-100) A9(-50,-100) A10(-150,-100) A11(-250,-100) A12(-350,-100) A13(-450,-100) A14(-550,-100) A15(-650,-100) A16(-750,-100) B1(750,0) B2(650,0) B3(550,0) B4(450,0) B5(350,0) B6(250,0) B7(150,0) B8(50,0) B9(-50,0) B10(-150,0) B11(-250,0) B12(-350,0) B13(-450,0) B14(-550,0) B15(-650,0) B16(-750,0) C2(650,100) C3(550,100) C4(450,100) C5(350,100) C6(250,100) C7(150,100) C8(50,100) C9(-50,100) C10(-150,100) C11(-250,100) C12(-350,100) C13(-450,100) C14(-550,100) C15(-650,100) C16(-750,100)
  rect 62x62 / inner round 60 / far side round 60 hole 39.37: C1(750,100)
  silkscreen extent -1073,-612 1073,-65
C0603#1 [mm]
  rect 0.9x0.9 smd: 1(-0.75,0) 2(0.75,0)
  Top pour cut-out: -0.381,0.508 0.381,0.508 0.381,-0.508 -0.381,-0.508
  silkscreen extent -1.52,-0.76 1.53,0.76
C0603#2 [mm]
  rect 0.9x0.9 smd: 1(-0.75,0) 2(0.75,0)
  Top pour cut-out: -0.178,0.508 0.152,0.508 0.152,-0.508 -0.178,-0.508
  silkscreen extent -1.52,-0.76 1.53,0.76
C1206 [mil]
  rect 65x65 smd: 1(0,0) 2(126,0)
  silkscreen extent -44,-40 170,40
C6032 [mil]
  rect 110x100 smd: 1(0,0) 2(210,0)
  silkscreen extent -79,-72 277,72
CE8X3.5 [mm]
  rect 2x2 / inner round 1.524 / far side round 1.524 hole 1: 1(-1.75,0)
  round 2 / inner round 1.524 / far side round 1.524 hole 1: 2(1.75,0)
  silkscreen extent -4.2,-4.2 4.2,4.2
CN2 [mm]
  rect 1.6x1.6 / inner round 1.524 / far side round 1.524 hole 1: 1(0,0)
  round 1.6 / inner round 1.524 / far side round 1.524 hole 1: 2(2.5,0)
  silkscreen extent -2.8,-3.8 5.3,2.6
CON5_2D54MM_G [mm]
  rect 1.6x1.6 / inner round 1.524 / far side round 1.524 hole 1: 1(0,0)
  round 1.6 / inner round 1.524 / far side round 1.524 hole 1: 2(2.5,0) 3(5,0) 4(7.5,0) 5(10,0)
  silkscreen extent -2.8,-3.8 12.8,2.6
CON8_2D54MM_G [mm]
  rect 1.6x1.6 / inner round 1.524 / far side round 1.524 hole 1: 1(0,0)
  round 1.6 / inner round 1.524 / far side round 1.524 hole 1: 2(2.54,0) 3(5.08,0) 4(7.62,0) 5(10.16,0) 6(12.7,0) 7(15.24,0) 8(17.78,0)
  silkscreen extent -2.8,-3.8 20.32,2.6
F15 [mm]
  round 2 hole 1: 1(0,0) 2(15,0)
  silkscreen extent 0.03,-2.01 14.5,2.06
FB0805 [mil]
  rect 60x55 smd: 1(0,0) 2(92,0)
  silkscreen extent -39,-34 131,34
H5007-H [mm]
  rect 0.6x2.2 smd: 1(-6.985,-8) 2(-5.715,-8) 3(-4.445,-8) 4(-3.175,-8) 5(-1.905,-8) 6(-0.635,-8) 7(0.635,-8) 8(1.905,-8) 9(3.175,-8) 10(4.445,-8) 11(5.715,-8) 12(6.985,-8) 13(6.985,8) 14(5.715,8) 15(4.445,8) 16(3.175,8) 17(1.905,8) 18(0.635,8) 19(-0.635,8) 20(-1.905,8) 21(-3.175,8) 22(-4.445,8) 23(-5.715,8) 24(-6.985,8)
  silkscreen extent -8.8,-10.63 8.82,8.3
HERDER2X13 [mm]
  rect 1.6x1.6 / inner round 1.524 / far side round 1.524 hole 1: 1(0,0)
  round 1.6 / inner round 1.524 / far side round 1.524 hole 1: 2(0,2.54) 3(2.54,0) 4(2.54,2.54) 5(5.08,0) 6(5.08,2.54) 7(7.62,0) 8(7.62,2.54) 9(10.16,0) 10(10.16,2.54) 11(12.7,0) 12(12.7,2.54) 13(15.24,0) 14(15.24,2.54) 15(17.78,0) 16(17.78,2.54) 17(20.32,0) 18(20.32,2.54) 19(22.86,0) 20(22.86,2.54) 21(25.4,0) 22(25.4,2.54) 23(27.94,0) 24(27.94,2.54) 25(30.48,0) 26(30.48,2.54)
  silkscreen extent -5.26,-3.23 35.74,6.46
HERDER5X2 [mm]
  rect 1.4x1.8 / inner round 1.524 / far side round 1.524 hole 1: 1(0,0)
  oval 1.4x1.8 / inner round 1.524 / far side round 1.524 hole 1: 2(0,2.54) 3(2.54,0) 4(2.54,2.54) 5(5.08,0) 6(5.08,2.54) 7(7.62,0) 8(7.62,2.54) 9(10.16,0) 10(10.16,2.54)
  silkscreen extent -2.02,-1.27 11.68,4.52
HERDER13X2-2.0 [mm]
  rect 1.2x1.6 hole 0.8: 1(0,0)
  oval 1.2x1.6 hole 0.8: 2(0,2) 3(2,0) 4(2,2) 5(4,0) 6(4,2) 7(6,0) 8(6,2) 9(8,0) 10(8,2) 11(10,0) 12(10,2) 13(12,0) 14(12,2) 15(14,0) 16(14,2) 17(16,0) 18(16,2) 19(18,0) 20(18,2) 21(20,0) 22(20,2) 23(22,0) 24(22,2) 25(24,0) 26(24,2)
  silkscreen extent -2.13,-1.98 25.5,4.32
HK [mm]
  round 3 / inner round 1.524 / far side round 1.524 hole 3.5: 1(-0.012,0.007)
  oval 2x1 / inner round 1.524 / far side round 1.524 hole 0.6: 2(3.063,0.007) 6(-3.062,0.007)
  oval 2x1 / inner round 1.524 / far side round 1.524 hole 0.6 rot 135: 3(2.238,-2.068)
  oval 1x2 / inner round 1.524 / far side round 1.524 hole 0.6: 4(0.013,-3.018) 8(-0.025,3.075)
  oval 2x1 / inner round 1.524 / far side round 1.524 hole 0.6 rot 45: 5(-2.262,-2.068) 9(2.238,2.107)
  oval 2x1 / inner round 1.524 / far side round 1.524 hole 0.6 rot 145: 7(-2.262,2.107)
  silkscreen extent -4.01,-3.99 3.99,4.01
L0603 [mm]
  rect 0.9x0.9 smd: 1(0,0.75) 2(0,-0.75)
  Top pour cut-out: -0.508,0.381 0.508,0.381 0.508,-0.381 -0.508,-0.381
  silkscreen extent -0.76,-1.52 0.76,1.52
LED0805 [mil]
  rect 60x60 smd: A(89.68,-0.39) K(-0.32,-0.39)
  silkscreen extent -60,-45 140,45
MPI6045 [mm]
  rect 1.5x4 smd: 1(-2.538,-0.007) 2(2.562,-0.007)
  silkscreen extent -3.49,-3.51 3.51,3.49
POWERPAKSO8 [mm]
  rect 1.8x0.61 smd: 1(0,0)
  oval 1.8x0.61 smd: 2(0,-1.27) 3(0,-2.54) 4(0,-3.81) 5(5.6,-3.81) 6(5.6,-2.54) 7(5.6,-1.27) 8(5.6,0)
  rect 3x4.425 smd: 9(3.425,-1.9)
  silkscreen extent 1.08,-4.69 4.52,0.9
QFN-48P-RTL8211 [mil]
  oval 8x30 smd mask+2: 1(-86.61,-114.96) 2(-70.87,-114.96) 3(-55.12,-114.96) 4(-39.37,-114.96) 5(-23.62,-114.96) 6(-7.87,-114.96) 7(7.87,-114.96) 8(23.62,-114.96) 9(39.37,-114.96) 10(55.12,-114.96) 11(70.87,-114.96) 12(86.61,-114.96) 25(86.61,114.96) 26(70.87,114.96) 27(55.12,114.96) 28(39.37,114.96) 29(23.62,114.96) 30(7.87,114.96) 31(-7.87,114.96) 32(-23.62,114.96) 33(-39.37,114.96) 34(-55.12,114.96) 35(-70.87,114.96) 36(-86.61,114.96)
  oval 30x8 smd mask+2: 13(114.96,-86.61) 14(114.96,-70.87) 15(114.96,-55.12) 16(114.96,-39.37) 17(114.96,-23.62) 18(114.96,-7.87) 19(114.96,7.87) 20(114.96,23.62) 21(114.96,39.37) 22(114.96,55.12) 23(114.96,70.87) 24(114.96,86.61) 37(-114.96,86.61) 38(-114.96,70.87) 39(-114.96,55.12) 40(-114.96,39.37) 41(-114.96,23.62) 42(-114.96,7.87) 43(-114.96,-7.87) 44(-114.96,-23.62) 45(-114.96,-39.37) 46(-114.96,-55.12) 47(-114.96,-70.87) 48(-114.96,-86.61)
  rect 175x175 / inner round 60 / far side round 60 hole 23.62: 49(0,0)
  silkscreen extent -177,-177 177,179
R0603 [mil]
  rect 32x36 smd: 1(-30,0) 2(30,0)
  Top pour cut-out: -15,20 15,20 15,-20 -15,-20
  silkscreen extent -60,-30 60,30
SCXO_7.0X5.0 [mm]
  rect 2.4x2.2 smd: 1(0.008,0.001)
  rect 2x1.8 smd: 2(5.088,0.001) 3(5.088,4.201) 4(0.008,4.201)
  silkscreen extent -2.48,-1.27 7.37,5.36
SIP4 [mm]
  rect 1.5x1.5 hole 0.9: 1(0.008,0.007)
  round 1.5 hole 0.9: 2(2.548,0.007) 3(5.088,0.007) 4(7.628,0.007)
  silkscreen extent -2.51,-2.96 10.14,2
SOT23 [mil]
  rect 40x45 smd: 1(-40,-50) 2(40,-50)
  rect 40x50 smd: 3(0,50)
  silkscreen extent -55,-50 55,26
SOT23_6_G [mil]
  rect 60x21.65 smd: 1(-59.06,37.4) 2(-59.06,0) 3(-59.06,-37.4) 4(59.06,-37.4) 5(59.06,0) 6(59.06,37.4)
  silkscreen extent -22,-59 22,61
SOT223 [mil]
  rect 45x65 smd: 1(-91,-125) 2(0,-125) 3(91,-125)
  rect 118x65 smd: 4(0,125)
  silkscreen extent -125,-65 125,65
TJC2-6 [mm]
  rect 3.5x4 hole 1.9: 1(0,0.007)
  oval 3.5x4 hole 1.9: 2(7.5,0.007) 3(12.5,0.007) 4(17.5,0.007) 5(22.5,0.007) 6(27.5,0.007)
  silkscreen extent -3.4,-3.55 31,3.56
TP_G [mil]
  round 40 smd: 1(0,0)
  silkscreen extent -30,-30 30,30
TQFP-100P [mil]
  rect 70x11 smd: 1(-0.73,-0.44)
  oval 70x11 smd: 2(-0.73,-20.12) 3(-0.73,-39.81) 4(-0.73,-59.49) 5(-0.73,-79.18) 6(-0.73,-98.86) 7(-0.73,-118.55) 8(-0.73,-138.23) 9(-0.73,-157.92) 10(-0.73,-177.6) 11(-0.73,-197.29) 12(-0.73,-216.97) 13(-0.73,-236.66) 14(-0.73,-256.34) 15(-0.73,-276.03) 16(-0.73,-295.71) 17(-0.73,-315.4) 18(-0.73,-335.08) 19(-0.73,-354.77) 20(-0.73,-374.45) 21(-0.73,-394.14) 22(-0.73,-413.82) 23(-0.73,-433.51) 24(-0.73,-453.19) 25(-0.73,-472.88) 51(605.57,-472.88) 52(605.57,-453.19) 53(605.57,-433.51) 54(605.57,-413.82) 55(605.57,-394.14) 56(605.57,-374.45) 57(605.57,-354.77) 58(605.57,-335.08) 59(605.57,-315.4) 60(605.57,-295.71) 61(605.57,-276.03) 62(605.57,-256.34) 63(605.57,-236.66) 64(605.57,-216.97) 65(605.57,-197.29) 66(605.57,-177.6) 67(605.57,-157.92) 68(605.57,-138.23) 69(605.57,-118.55) 70(605.57,-98.86) 71(605.57,-79.18) 72(605.57,-59.49) 73(605.57,-39.81) 74(605.57,-20.12) 75(605.57,-0.44)
  oval 11x70 smd: 26(66.2,-539.81) 27(85.89,-539.81) 28(105.57,-539.81) 29(125.26,-539.81) 30(144.94,-539.81) 31(164.63,-539.81) 32(184.31,-539.81) 33(204,-539.81) 34(223.68,-539.81) 35(243.37,-539.81) 36(263.05,-539.81) 37(282.74,-539.81) 38(302.42,-539.81) 39(322.11,-539.81) 40(341.79,-539.81) 41(361.48,-539.81) 42(381.16,-539.81) 43(400.85,-539.81) 44(420.53,-539.81) 45(440.22,-539.81) 46(459.9,-539.81) 47(479.59,-539.81) 48(499.27,-539.81) 49(518.96,-539.81) 50(538.64,-539.81) 76(538.64,66.49) 77(518.96,66.49) 78(499.27,66.49) 79(479.59,66.49) 80(459.9,66.49) 81(440.22,66.49) 82(420.53,66.49) 83(400.85,66.49) 84(381.16,66.49) 85(361.48,66.49) 86(341.79,66.49) 87(322.11,66.49) 88(302.42,66.49) 89(282.74,66.49) 90(263.05,66.49) 91(243.37,66.49) 92(223.68,66.49) 93(204,66.49) 94(184.31,66.49) 95(164.63,66.49) 96(144.94,66.49) 97(125.26,66.49) 98(105.57,66.49) 99(85.89,66.49) 100(66.2,66.49)
  silkscreen extent -71,-608 674,135
TSSOP-8 [mm]
  rect 1.5x0.28 smd: 1(0.006,-0.001)
  oval 1.5x0.28 smd: 2(0.006,-0.651) 3(0.006,-1.301) 4(0.006,-1.951) 5(6.306,-1.951) 6(6.306,-1.301) 7(6.306,-0.651) 8(6.306,-0.001)
  silkscreen extent -0.14,-2.18 5.37,0.92

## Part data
B1 B2 B3 B4 B5 B6 B7 B8 B9 B10 B11 B12 B13 F1 F2 L1 L2 L3 L4 L5: library part "CHOKE TORROID_0"
C1 C3 C6 C61 C95 C129: library part "CAP POL"
C2 C4 C5 C7 C8 C9 C10 C11 C16 C17 C18 C19 C20 C300 C301 C302 C303 C304 C305: library part "CAP NP"
C12 C13 C14 C15 C21 C22 C23 C24 C25 C26 C27 C28 C29 C30 C31 C32 C33 C34 C35 C36 C37 C38 C39 C40 C41 C42 C43 C44 C45 C46 C47 C48 C49 C50 C51 C52 C53 C54 C55 C56 C57 C58 C59 C60 C62 C63 C64 C65 C66 C67 C68 C69 C70 C71 C72 C73 C74 C75 C76 C77 C78 C79 C80 C81 C82 C83 C84 C85 C86 C87 C88 C89 C90 C91 C92 C93 C94 C96 C97 C98 C99 C100 C101 C102 C103 C104 C105 C106 C107 C108 C109 C110 C111 C112 C113 C114 C115 C116 C117 C118 C119 C120 C121 C122 C123 C124 C125 C126 C127 C128: library part "CAP NP_Dup1"
J1: library part CON8_0
J2 J3 J4: library part CON26A_0
J7 J9 J10 J11 J12 J13 J14: library part CON8_1
JTAG1: library part CON10A_0
LED1: library part LED_1
LED2 LED3 LED4: library part LED_0
M1 M2 M3 M4 M5 M6 M7 M8: library part GEN35
PWR1 PWR2: library part POWER_4P
Q1 Q6 Q11: library part "MOSFET P_0"
Q3 Q5 Q8 Q10 Q13 Q15: library part 2N3904
R1 R2 R3 R4 R5 R6 R8 R9 R10 R11 R47 R49 R58 R65 R73 R74 R107 R109 R118 R127 R133 R134 R167 R169 R178 R186 R193 R194: library part R
R7 R12 R13 R14 R15 R16 R17 R18 R19 R20 R21 R22 R23 R24 R25 R26 R27 R28 R29 R30 R31 R32 R33 R34 R35 R36 R37 R38 R39 R40 R41 R42 R43 R44 R45 R46 R48 R50 R51 R52 R53 R54 R55 R56 R59 R60 R61 R62 R63 R64 R66 R67 R68 R70 R71 R72 R77 R80 R81 R82 R83 R84 R85 R86 R87 R88 R89 R90 R91 R92 R93 R94 R95 R96 R97 R98 R99 R100 R101 R102 R103 R104 R105 R106 R108 R110 R111 R112 R113 R114 R115 R116 R119 R120 R121 R122 R123 R124 R125 R126 R128 R130 R131 R132 R136 R140 R141 R142 R143 R144 R145 R146 R147 R148 R149 R150 R151 R152 R153 R154 R155 R156 R157 R158 R159 R160 R161 R162 R163 R164 R165 R166 R168 R170 R171 R172 R173 R174 R175 R176 R179 R180 R181 R182 R183 R184 R185 R187 R188 R190 R191 R192 R197 R200 R201 R202 R203 R300 R301 R302 R303 R304 R400 R401 R402 R403 R404 R405 R406 R407 R408 R409 R410 R411 R412 R413 R414 R415 R416 R417 R424 R425 R432 R433 R500: library part R_Dup1
R75 R76 R135 R137 R195 R196 R418 R419 R420 R421 R422 R423 R426 R427 R428 R429 R430 R431: library part R_1
T1 T2 T3: library part "PULSE H5007_0"
U5: library part SY8120
U6: library part AS1117-X_0
U8: library part RTL8211D_2
U9: library part AS1117-X_3
U11 U14: library part RTL8211D_1
U12: library part AS1117-X_1
U15: library part AS1117-X_2
Y1: library part SCXO

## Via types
v1: diameter 18, hole 12, Top to Bottom, 768 vias
v2: diameter 24, hole 16, Top to Bottom, 34 vias
v3: diameter 30, hole 20, Top to Bottom, 27 vias
v4: diameter 40, hole 30, Top to Bottom, 2 vias
v5: diameter 24, hole 14, Top to Bottom, 1 vias

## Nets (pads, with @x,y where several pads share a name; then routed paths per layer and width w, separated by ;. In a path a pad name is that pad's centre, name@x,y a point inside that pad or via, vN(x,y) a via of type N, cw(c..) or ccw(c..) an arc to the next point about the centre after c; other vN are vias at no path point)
5V0: B12.2 C12.1 C13.1 J8.9 J8.10 J8.11 J8.12 L2.2 Q1.2 Q6.2 Q11.2 R49.2 R58.1 R109.2 R118.1 R169.2 R178.1 U6.3 | length 1623.8
  Top w18: R118.1@320,-1390 345,-1390 360,-1375 Q6.2@360,-1340
  Top w20: B12.2@6245,-1655.47 6245,-1630 6290,-1585 v1(6310,-1585)
  Top w30: Q6.2@360,-1340 R109.2@425,-1340 v3(425,-1380) ; R49.2@3430,-780 3430,-745 ; R58.1@3430,-715 3430,-745 ; Q1.2@3510,-740 v3(3465,-740) 3435,-740 3430,-745 ; U6.3@6425,-244 6445.18,-244 6483.18,-282 6517,-282 C13.1@6520,-285 6520,-225.47 C12.1@6520.47,-225 6520.47,-152.47 L2.2@6518,-150 6503,-135 v3(6460,-135) ; v3(6425,-170) v3(6460,-170) v3(6460,-135) ; v3(6425,-135) v3(6460,-135) ; v3(7695,-765) 7765,-765 ; R169.2@7745,-765 7765,-765 ; R178.1@7805,-715 Q11.2@7805,-765 7765,-765
  VCC w20: v1(6310,-1585) 6615,-1585 6685,-1515 v1(6685,-1335)
12VIN: C3.1 C4.1 C16.1 C17.1 C61.1 C95.1 C129.1 C302.1 C303.1 C304.1 C305.1 F1.1 F2.1 J8.1 J8.2 J8.3 J8.4 J8.5 J8.6 J8.7 J8.8 R2.1 R3.1 R8.1 R77.2 R136.2 R197.2 U1.5 U1.6 U1.7 U1.8 U1.9 U2.5 U2.6 U2.7 U2.8 U2.9 U3.6 U4.6 U5.5 U10.1 U10.2 U10.3 U13.1 U13.2 U13.3 U16.1 U16.2 U16.3 | length 4212.1
  Top w5: 188.9,-800 209.45,-820.55 214.45,-825.55 220,-831.1 230,-831.1 330.24,-831.1 330.24,-825 ; U13.1@330.24,-765.21 330.24,-825 ; U13.2@380.24,-765.21 380.24,-825 ; 430.24,-830 385,-830 380.24,-825.24 380.24,-825 ; 3275.26,-430.21 3282.21,-437.16 3289.79,-444.74 3293.15,-444.74 3304.25,-455.84 3430,-455.84 R77.2@3518.15,-455.84 ; U10.3@3648.15,-465.84 3528.15,-465.84 R77.2@3518.15,-455.84 ; U10.2@3648.15,-415.84 3533.15,-415.84 ; U10.1@3648.15,-365.84 3583.15,-365.84 3533.15,-415.84 ; U5.5@6912.72,-298.18 7080,-298.18 7152.69,-298.18 7152.69,-293.18 7093.66,-293.18 7095.92,-290.92 C302.1@7105,-281.84 ; 7583.9,-340 7618.9,-375 C305.1@7665,-375 7725,-375 7725.16,-374.84 7776.15,-374.84 ; U16.3@7841.15,-374.84 7776.15,-374.84 ; U16.2@7841.15,-324.84 7776.15,-324.84 ; U16.1@7841.15,-274.84 7796.15,-274.84 7776.15,-294.84 7776.15,-324.84 ; 330.24,-825 380.24,-825 ; R77.2@3518.15,-455.84 3518.15,-430.84 3533.15,-415.84 ; 7776.15,-374.84 7776.15,-324.84
  Top w10: U2.9@10365.16,-1190.2 10375.16,-1180.2 10380.18,-1175.18 10410,-1145.35 10410,-1120 U2.9@10410,-1115
  Top w12: U2.9@10410,-1115 10410,-1036.23 10430,-1016.23 U4.6@10523.26,-1016.23 ; U1.9@10670.16,-795.2 10695.56,-769.79 10710,-755.35 10710,-730 10710,-635 10728.77,-616.23 U3.6@10818.26,-616.23
  Top w15: R3.1@10215,-1115 10165,-1115 10150,-1100 10150,-883.9 C3.1@10318.9,-715
  Top w18: R136.2@425,-855 430.24,-849.76 430.24,-830 U13.3@430.24,-765.21 ; J8.4@10354.33,-275.59 J8.2@10275.59,-275.59 J8.1@10275.59,-354.33 J8.3@10354.33,-354.33 10354.33,-679.57 C3.1@10318.9,-715 R2.1@10495,-715 ; R2.1@10500,-720 U1.5@10584.53,-720
  Top w24: R3.1@10215,-1115 U2.5@10299.53,-1115
  Top w30: 7118.66,-278.18 7121.84,-275 C16.1@7210,-275 ; C16.1@7210,-315 C16.1@7210,-275 ; C16.1@7210,-240 C16.1@7210,-275
  Top w80: 7118.66,-278.18 7122.82,-282.35
  other v2: 10370,-1260 10420,-1260 10370,-1215 10420,-1215 10370,-1165 10415,-1165 10370,-1120 10420,-1120 10655,-860 10700,-860 10655,-815 10700,-815 10698.06,-772.29 10655,-770 10655,-730 10700,-730
  other v3: 10285,-535 10325,-535 10285,-500 10325,-500 10285,-465 10325,-465 7275,-315 7275,-275 7275,-240
A3V3A: B5.1 C41.1 C42.1 C43.1 U8.6 U8.41 | length 634.9
  Top w8: v1(4996.85,-674.16) 5019.07,-674.16 5026.85,-666.38 U8.41@5070.04,-666.38 ; v1@5176.85,-879.16 5176.85,-805.24 U8.6@5177.13,-804.96
  Bottom w12: C43.1@4961.38,-694.16 4976.85,-694.16 v1(4996.85,-674.16)
  Bottom w15: C42.1@4961.38,-764.16 4961.38,-769.16 4961.38,-793.69 5006.85,-839.16 C41.1@5171.38,-839.16 ; C41.1@5176.85,-844.16 5176.85,-874.16 v1(5181.85,-879.16)
  Bottom w18: 4961.38,-769.16 4961.38,-694.16 B5.1@4961.38,-624.16
A3V3D: B3.2 B5.2 C31.1 C32.1 C33.1 C34.1 C55.1 C56.1 R34.1 R36.1 R41.1 R46.2 R47.1 R48.2 R50.2 R52.2 R53.2 R54.2 R59.2 R63.2 R66.2 R68.2 R71.2 R409.2 R410.2 R411.2 U8.15 U8.21 U8.37 U9.2 U9.4 | length 5764.6
  Top w8: R54.2@4730,-540 4755,-565 4790,-565 v1(4830,-525) ; v1(4845,-475) 4845,-430 4860,-415 R34.1@4880,-415 ; v1(4995,-595) 5007.69,-595 5016.08,-603.39 U8.37@5070.04,-603.39 ; U8.21@5299.96,-650.63 5351.85,-650.63 v1@5355.38,-650.63 ; v1(5351.85,-649.16) 5351.85,-558.15 5360,-550 R46.2@5375,-550 5365,-540 v1(5365,-525) ; R71.2@5455,-455 v1(5475,-455) R68.2@5500,-455 ; R66.2@5595,-455 R59.2@5635,-455 ; R66.2@5600,-450 v1(5600,-430)
  Top w10: v1(4700,-415) R53.2@4730,-415 ; U8.15@5299.96,-745.12 5353.81,-745.12 v1(5355.85,-747.16)
  Top w12: R63.2@4625,-550 4625,-535 4645,-515 v1(4700,-515) 4725,-540 R54.2@4730,-540 ; v3(4650,-790) 4650,-675 4665,-660 v1(4700,-660) 4850,-660 4875,-635 v1(4875,-625) 4895,-605 R48.2@4920,-605 ; v1(5355,-870) v1(5355,-796.7)
  Top w15: R36.1@3205,-1370 R41.1@3245,-1370 R52.2@3285,-1370 3285,-1030 3355,-960 4200,-960 4250,-910 4250,-790 C56.1@4250,-789.53 ; v1(4570,-515) 4585,-530 R50.2@4585,-550 R63.2@4625,-550
  Top w18: B3.2@4710,-809.53 4710,-950 4780,-1020 v1(5120,-1020)
  Top w32: U9.4@4150,-790 4250,-790 v3(4465,-790) ; v3(4650,-790) 4665,-790 4684.53,-809.53 B3.2@4710,-809.53
  Top w35: R47.1@3805,-780 3880,-780 U9.2@3885,-775
  Bottom w8: v1(4830,-525) 4845,-510 v1(4845,-475) ; v1@5365,-520 5430,-455 v1(5475,-455) 5575,-455 v1(5600,-430)
  Bottom w12: R411.2@4360,-490 4360,-535 4370,-545 4440,-545 ; R410.2@4440,-490 4440,-545 ; R409.2@4570,-490 v1(4570,-515) 4570,-525 4550,-545 4440,-545 ; v1(4700,-660) v1(4700,-515) v1(4700,-415) ; v1@4876.31,-623.69 B5.2@4901.85,-623.69 ; B5.2@4902.32,-624.16 B5.2@4901.85,-623.69 ; C33.1@5020,-595 v1(4995,-595) 4930.54,-595 B5.2@4901.85,-623.69 ; C31.1@5326.38,-744.16 5352.85,-744.16 v1(5355.85,-747.16) 5355.85,-795.85 v1(5355,-796.7) ; C32.1@5326.38,-657.16 5343.85,-657.16 v1(5351.85,-649.16)
  Bottom w16: C31.1@5326.38,-744.16 C32.1@5326.38,-657.16 C32.1@5326.85,-656.69
  Bottom w18: v1(5120,-1020) 5205,-1020 v1(5355,-870)
  Bottom w32: v3(4465,-790) v3(4650,-790)
A5V: C57.1 C58.1 Q1.3 R47.2 R49.1 U9.3 | length 465.8
  Top w32: R49.1@3430,-840 Q1.3@3550,-840 3830,-840 3856,-866 U9.3@3885,-866
A_MCLK: JP1.A3 R60.1 | length 458.3
  Top w5: JP1.A3@4587.8,-115.41 4635,-162.61 4635,-380 v1(4630,-385) ; v1(4670,-385) 4765,-385 4770,-390 R60.1@4770,-415
  Bottom w5: v1(4630,-385) v1(4670,-385)
A_MDIO: JP1.A4 R62.1 | length 319.4
  Top w5: R62.1@4650,-415 4650,-375 4645,-370 4645,-158.2 JP1.A4@4687.8,-115.41
A_MX1_N: J2.14 T1.22 | length 4223
  Top w6: v1(2885,-1955) 3590,-1955 3685,-1860 3685,-1575 3740,-1520 5150,-1520 5235,-1605 5235,-1839.44 5304.56,-1909 5875.44,-1909 5909.81,-1874.64 ccw(c5905.99,-1870.82) 5909.8,-1867 5904.24,-1861.44 cw(c5908.06,-1857.62) 5904.24,-1853.8 5905.09,-1852.96 cw(c5908.91,-1856.77) 5912.73,-1852.96 5918.29,-1858.52 ccw(c5922.11,-1854.7) 5925.93,-1858.52 5945.72,-1838.72 5945.72,-1815.72 5926.14,-1796.14 5926.14,-1770.8 T1.22@5926.14,-1745.8
  Top w8: T1.22@5925,-1771.94 T1.22@5926.14,-1770.8
  Bottom w6: J2.14@2835,-1671.65 2880,-1716.65 2880,-1825.6 ccw(c2885.4,-1825.6) 2885.4,-1831 2905.64,-1831 cw(c2905.64,-1836.4) 2911.04,-1836.4 2911.04,-1837.6 cw(c2905.64,-1837.6) 2905.64,-1843 2885.4,-1843 ccw(c2885.4,-1848.4) 2880,-1848.4 2880,-1950 v1(2885,-1955)
A_MX1_P: J2.13 T1.23 | length 4226.2
  Top w6: v1(2870,-1975) 2895,-1975 2904,-1966 3594.56,-1966 3696,-1864.56 3696,-1579.56 3744.56,-1531 5145.44,-1531 5224,-1609.56 5224,-1844 5300,-1920 5880,-1920 5908.2,-1891.8 cw(c5912.01,-1895.62) 5915.83,-1891.8 5933.33,-1909.31 ccw(c5937.15,-1905.49) 5940.97,-1909.31 5941.82,-1908.46 ccw(c5938,-1904.64) 5941.82,-1900.82 5924.32,-1883.32 cw(c5928.14,-1879.5) 5924.32,-1875.68 5925.17,-1874.83 cw(c5928.98,-1878.65) 5932.8,-1874.83 5950.3,-1892.33 ccw(c5954.12,-1888.52) 5957.94,-1892.33 5958.79,-1891.49 ccw(c5954.97,-1887.67) 5958.79,-1883.85 5941.29,-1866.35 cw(c5945.11,-1862.53) 5941.29,-1858.71 5956.72,-1843.28 5956.72,-1809.42 5976.14,-1790 T1.23@5976.14,-1770.8
  Top w8: T1.23@5976.14,-1798.86 5976.14,-1790 T1.23@5976.14,-1770.8
  Bottom w6: J2.13@2835,-1771.65 2851.65,-1771.65 2868,-1788 2868,-1962.04 2870,-1964.04 2870,-1970 v1@2867.5,-1972.5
